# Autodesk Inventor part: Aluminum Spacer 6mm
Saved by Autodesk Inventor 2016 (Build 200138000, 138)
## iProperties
Created: 2016-01
Part Number: Aluminum Spacer 6mm
Material: Generic
Document SubType Name: Modeling
Designer: John
Density: 1 g/cm^3
Appearance: Default
Author: John
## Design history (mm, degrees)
feature "CHAMFER1"
body "Solid1"
